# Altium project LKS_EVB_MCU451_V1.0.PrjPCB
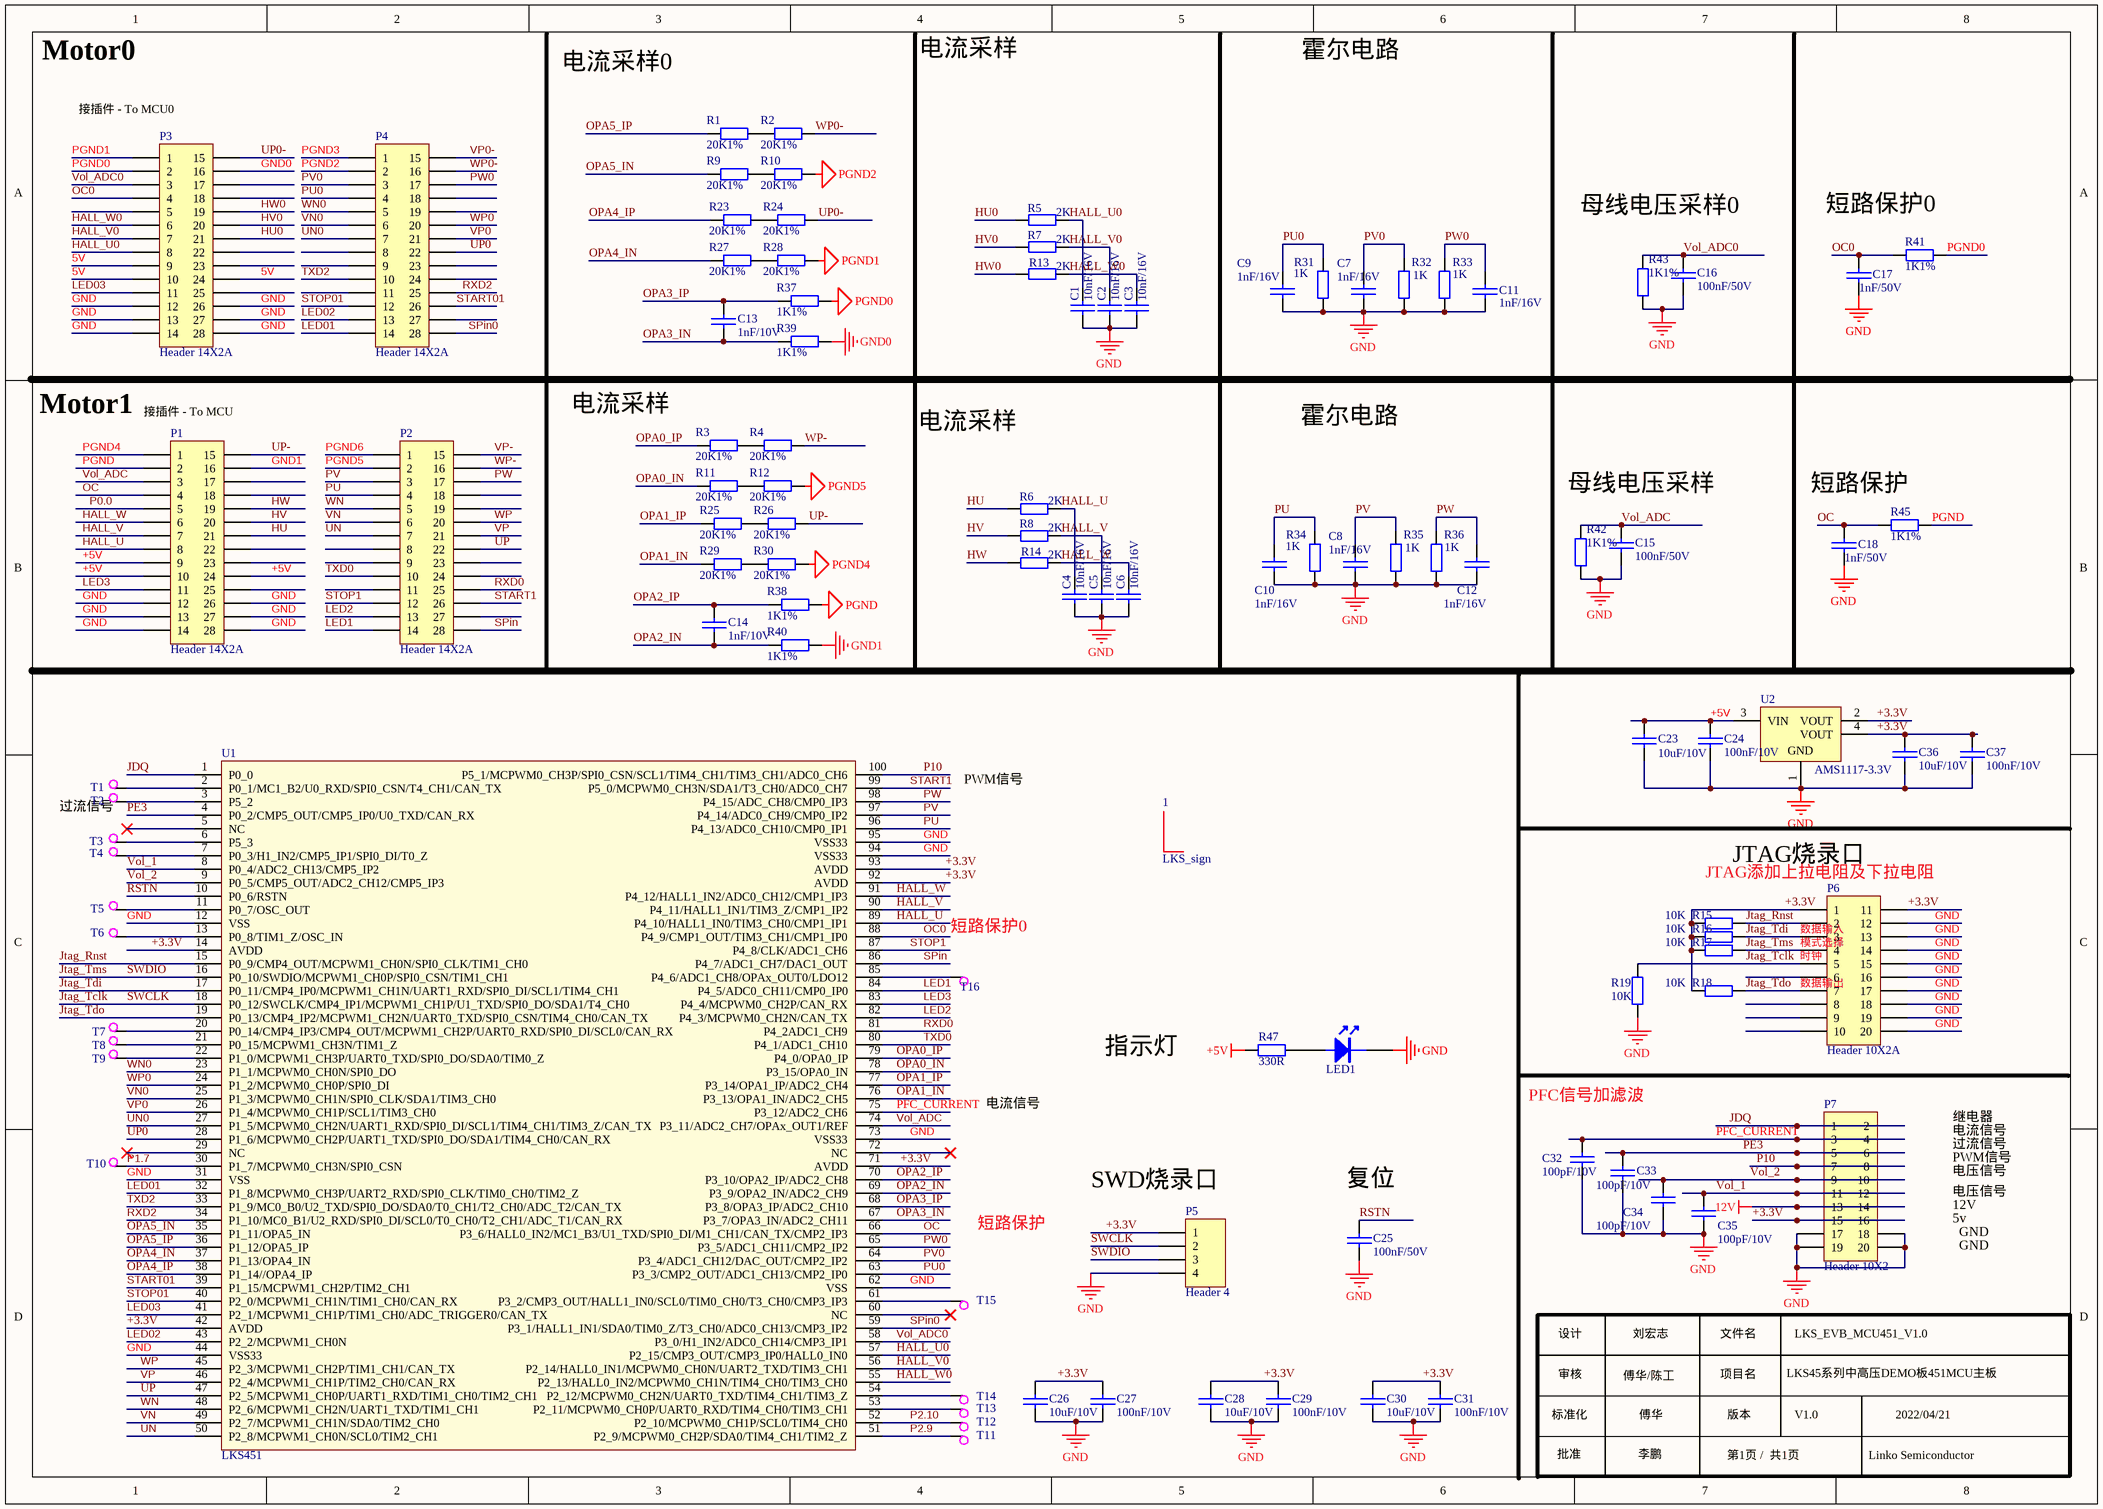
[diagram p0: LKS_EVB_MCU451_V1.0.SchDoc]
1 sheet, 102 parts. Net scope: global (net labels, ports and power ports of the same name join across sheets).
Board file: LKS_EVB_MCU451_V1.0.PcbDoc

## Sheet LKS_EVB_MCU451_V1.0.SchDoc
size A3

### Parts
1  LKS_sign  [LKS_LOGO2]
C1  10nF/16V  [0603C]
C2  10nF/16V  [0603C]
C3  10nF/16V  [0603C]
C4  10nF/16V  [0603C]
C5  10nF/16V  [0603C]
C6  10nF/16V  [0603C]
C7  1nF/16V  [0603C]
C8  1nF/16V  [0603C]
C9  1nF/16V  [0603C]
C10  1nF/16V  [0603C]
C11  1nF/16V  [0603C]
C12  1nF/16V  [0603C]
C13  1nF/10V  [0603C]
C14  1nF/10V  [0603C]
C15  100nF/50V  [0603C]
C16  100nF/50V  [0603C]
C17  1nF/50V  [0603C]
C18  1nF/50V  [0603C]
C23  10uF/10V  [0603C]
C24  100nF/10V  [0603C]
C25  100nF/50V  [0603C]
C26  10uF/10V  [0603C]
C27  100nF/10V  [0603C]
C28  10uF/10V  [0603C]
C29  100nF/10V  [0603C]
C30  10uF/10V  [0603C]
C31  100nF/10V  [0603C]
C32  100pF/10V  [0603C]
C33  100pF/10V  [0603C]
C34  100pF/10V  [0603C]
C35  100pF/10V  [0603C]
C36  10uF/10V  [0603C]
C37  100nF/10V  [0603C]
LED1  LED  [0603D]  (value not drawn)
P1  Header 14X2A  [HDR2X14_CEN]
P2  Header 14X2A  [HDR2X14_CEN]
P3  Header 14X2A  [HDR2X14_CEN]
P4  Header 14X2A  [HDR2X14_CEN]
P5  Header 4  [HDR1X4]
P6  Header 10X2A  [HDR2X10_CEN]
P7  Header 10X2  [HDR2X10]
R1  20K1%  [0603R]
R2  20K1%  [0603R]
R3  20K1%  [0603R]
R4  20K1%  [0603R]
R5  2K  [0603R]
R6  2K  [0603R]
R7  2K  [0603R]
R8  2K  [0603R]
R9  20K1%  [0603R]
R10  20K1%  [0603R]
R11  20K1%  [0603R]
R12  20K1%  [0603R]
R13  2K  [0603R]
R14  2K  [0603R]
R15  10K  [0603R]
R16  10K  [0603R]
R17  10K  [0603R]
R18  10K  [0603R]
R19  10K  [0603R]
R23  20K1%  [0603R]
R24  20K1%  [0603R]
R25  20K1%  [0603R]
R26  20K1%  [0603R]
R27  20K1%  [0603R]
R28  20K1%  [0603R]
R29  20K1%  [0603R]
R30  20K1%  [0603R]
R31  1K  [0603R]
R32  1K  [0603R]
R33  1K  [0603R]
R34  1K  [0603R]
R35  1K  [0603R]
R36  1K  [0603R]
R37  1K1%  [0603R]
R38  1K1%  [0603R]
R39  1K1%  [0603R]
R40  1K1%  [0603R]
R41  1K1%  [0603R]
R42  1K1%  [0603R]
R43  1K1%  [0603R]
R45  1K1%  [0603R]
R47  330R  [0603R]
T1  TestP  [TP-40]  (value not drawn)
T2  TestP  [TP-40]  (value not drawn)
T3  TestP  [TP-40]  (value not drawn)
T4  TestP  [TP-40]  (value not drawn)
T5  TestP  [TP-40]  (value not drawn)
T6  TestP  [TP-40]  (value not drawn)
T7  TestP  [TP-40]  (value not drawn)
T8  TestP  [TP-40]  (value not drawn)
T9  TestP  [TP-40]  (value not drawn)
T10  TestP  [TP-40]  (value not drawn)
T11  TestP  [TP-40]  (value not drawn)
T12  TestP  [TP-40]  (value not drawn)
T13  TestP  [TP-40]  (value not drawn)
T14  TestP  [TP-40]  (value not drawn)
T15  TestP  [TP-40]  (value not drawn)
T16  TestP  [TP-40]  (value not drawn)
U1  LKS451  [LQFP_100N]
U2  AMS1117-3.3V  [DCY0004A_M]

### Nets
12V: P7.13 P7.14
+5V: C23.1 C24.1 P1.9 P1.10 P1.24 R47.1 U2.3(VIN)
GND: C1.2 C2.2 C3.2 C4.2 C5.2 C6.2 C7.2 C8.2 C9.2 C10.2 C11.2 C12.2 C15.1 C16.1 C17.1 C18.1 C23.2 C24.2 C25.2 C26.2 C27.2 C28.2 C29.2 C30.2 C31.2 C32.2 C33.2 C34.2 C35.2 C36.2 C37.2 LED1.2(K) P1.12 P1.13 P1.14 P1.26 P1.27 P1.28 P3.12 P3.13 P3.14 P3.26 P3.27 P3.28 P5.4 P6.12 P6.13 P6.14 P6.15 P6.16 P6.17 P6.18 P6.19 P6.20 P7.17 P7.18 P7.19 P7.20 R19.1 R31.2 R32.2 R33.2 R34.2 R35.2 R36.2 R42.1 R43.1 U1.12(VSS) U1.31(VSS) U1.44(VSS33) U1.62(VSS) U1.73(VSS33) U1.94(VSS33) U1.95(VSS33) U2.1(GND)
GND0: P3.16 R39.1
GND1: P1.16 R40.1
PGND: P1.2 R38.1 R45.2
PGND0: P3.2 R37.1 R41.2
PGND1: P3.1 R28.1
PGND2: P4.2 R10.1
PGND4: P1.1 R30.1
PGND5: P2.2 R12.1
5V: P3.9 P3.10 P3.24
+3.3V: C26.1 C27.1 C28.1 C29.1 C30.1 C31.1 C36.1 C37.1 P5.1 P6.1 P6.11 P7.15 P7.16 R15.1 R16.1 R17.1 R18.1 U1.14(AVDD) U1.42(AVDD) U1.71(AVDD) U1.92(AVDD) U1.93(AVDD) U2.2(VOUT) U2.4(VOUT)
HALL_U: C4.1 P1.8 R6.2 U1.89(P4_10/HALL1_IN0/TIM3_CH0/CMP1_IP1)
HALL_U0: C1.1 P3.8 R5.2 U1.57(P2_15/CMP3_OUT/CMP3_IP0/HALL0_IN0)
HALL_V: C5.1 P1.7 R8.2 U1.90(P4_11/HALL1_IN1/TIM3_Z/CMP1_IP2)
HALL_V0: C2.1 P3.7 R7.2 U1.56(P2_14/HALL0_IN1/MCPWM0_CH0N/UART2_TXD/TIM3_CH1)
HALL_W: C6.1 P1.6 R14.2 U1.91(P4_12/HALL1_IN2/ADC0_CH12/CMP1_IP3)
HALL_W0: C3.1 P3.6 R13.2 U1.55(P2_13/HALL0_IN2/MCPWM0_CH1N/TIM4_CH0/TIM3_CH0)
HU: P1.21 R6.1
HU0: P3.21 R5.1
HV: P1.20 R8.1
HV0: P3.20 R7.1
HW: P1.19 R14.1
HW0: P3.19 R13.1
JDQ: P7.1 P7.2 U1.1(P0_0)
Jtag_Rnst: P6.2 R15.2 U1.15(P0_9/CMP4_OUT/MCPWM1_CH0N/SPI0_CLK/TIM1_CH0)
Jtag_Tclk: P5.2 P6.5 R19.2 U1.18(P0_12/SWCLK/CMP4_IP1/MCPWM1_CH1P/U1_TXD/SPI0_DO/SDA1/T4_CH0)  [also labelled SWCLK]
Jtag_Tdi: P6.3 R16.2 U1.17(P0_11/CMP4_IP0/MCPWM1_CH1N/UART1_RXD/SPI0_DI/SCL1/TIM4_CH1)
Jtag_Tdo: P6.7 R18.2 U1.19(P0_13/CMP4_IP2/MCPWM1_CH2N/UART0_TXD/SPI0_CSN/TIM4_CH0/CAN_TX)
Jtag_Tms: P5.3 P6.4 R17.2 U1.16(P0_10/SWDIO/MCPWM1_CH0P/SPI0_CSN/TIM1_CH1)  [also labelled SWDIO]
LED01: P4.14 U1.32(P1_8/MCPWM0_CH3P/UART2_RXD/SPI0_CLK/TIM0_CH0/TIM2_Z)
LED1: P2.14 U1.84(P4_5/ADC0_CH11/CMP0_IP0)
LED02: P4.13 U1.43(P2_2/MCPWM1_CH0N)
LED2: P2.13 U1.82(P4_3/MCPWM0_CH2N/CAN_TX)
LED03: P3.11 U1.41(P2_1/MCPWM1_CH1P/TIM1_CH0/ADC_TRIGGER0/CAN_TX)
LED3: P1.11 U1.83(P4_4/MCPWM0_CH2P/CAN_RX)
OC: C18.2 P1.4 R45.1 U1.66(P3_6/HALL0_IN2/MC1_B3/U1_TXD/SPI0_DI/M1_CH1/CAN_TX/CMP2_IP3)
OC0: C17.2 P3.4 R41.1 U1.88(P4_9/CMP1_OUT/TIM3_CH1/CMP1_IP0)
OPA0_IN: R11.2 U1.78(P3_15/OPA0_IN)
OPA0_IP: R3.2 U1.79(P4_0/OPA0_IP)
OPA1_IN: R29.2 U1.76(P3_13/OPA1_IN/ADC2_CH5)
OPA1_IP: R25.2 U1.77(P3_14/OPA1_IP/ADC2_CH4)
OPA2_IN: C14.2 R40.2 U1.69(P3_9/OPA2_IN/ADC2_CH9)
OPA2_IP: C14.1 R38.2 U1.70(P3_10/OPA2_IP/ADC2_CH8)
OPA3_IN: C13.2 R39.2 U1.67(P3_7/OPA3_IN/ADC2_CH11)
OPA3_IP: C13.1 R37.2 U1.68(P3_8/OPA3_IP/ADC2_CH10)
OPA4_IN: R27.2 U1.37(P1_13/OPA4_IN)
OPA4_IP: R23.2 U1.38(P1_14//OPA4_IP)
OPA5_IN: R9.2 U1.35(P1_11/OPA5_IN)
OPA5_IP: R1.2 U1.36(P1_12/OPA5_IP)
P0.0: P1.5
P1.7: T10.1 U1.30(P1_7/MCPWM0_CH3N/SPI0_CSN)
P2.9: T11.1 U1.51(P2_9/MCPWM0_CH2P/SDA0/TIM4_CH1/TIM2_Z)
P2.10: T12.1 U1.52(P2_10/MCPWM0_CH1P/SCL0/TIM4_CH0)
P10: P7.7 P7.8 U1.100(P5_1/MCPWM0_CH3P/SPI0_CSN/SCL1/TIM4_CH1/TIM3_CH1/ADC0_CH6)
PE3: C33.1 P7.5 P7.6 U1.4(P0_2/CMP5_OUT/CMP5_IP0/U0_TXD/CAN_RX)
PFC_CURRENT: C32.1 P7.3 P7.4 U1.75(P3_12/ADC2_CH6)
PGND3: P4.1
PGND6: P2.1
PU: C10.1 P2.4 R34.1 U1.96(P4_13/ADC0_CH10/CMP0_IP1)
PU0: C9.1 P4.4 R31.1 U1.63(P3_3/CMP2_OUT/ADC1_CH13/CMP2_IP0)
PV: C8.1 P2.3 R35.1 U1.97(P4_14/ADC0_CH9/CMP0_IP2)
PV0: C7.1 P4.3 R32.1 U1.64(P3_4/ADC1_CH12/DAC_OUT/CMP2_IP2)
PW: C12.1 P2.17 R36.1 U1.98(P4_15/ADC_CH8/CMP0_IP3)
PW0: C11.1 P4.17 R33.1 U1.65(P3_5/ADC1_CH11/CMP2_IP2)
RSTN: C25.1 U1.10(P0_6/RSTN)
RXD0: P2.25 U1.81(P4_2ADC1_CH9)
RXD2: P4.25 U1.34(P1_10/MC0_B1/U2_RXD/SPI0_DI/SCL0/T0_CH0/T2_CH1/ADC_T1/CAN_RX)
SPin: P2.28 U1.86(P4_7/ADC1_CH7/DAC1_OUT)
SPin0: P4.28 U1.59(P3_1/HALL1_IN1/SDA0/TIM0_Z/T3_CH0/ADC0_CH13/CMP3_IP2)
START01: P4.26 U1.39(P1_15/MCPWM1_CH2P/TIM2_CH1)
START1: P2.26 U1.99(P5_0/MCPWM0_CH3N/SDA1/T3_CH0/ADC0_CH7)
STOP01: P4.12 U1.40(P2_0/MCPWM1_CH1N/TIM1_CH0/CAN_RX)
STOP1: P2.12 U1.87(P4_8/CLK/ADC1_CH6)
TXD0: P2.10 U1.80(P4_1/ADC1_CH10)
TXD2: P4.10 U1.33(P1_9/MC0_B0/U2_TXD/SPI0_DO/SDA0/T0_CH1/T2_CH0/ADC_T2/CAN_TX)
UN: P2.7 U1.50(P2_8/MCPWM1_CH0N/SCL0/TIM2_CH1)
UN0: P4.7 U1.27(P1_5/MCPWM0_CH2N/UART1_RXD/SPI0_DI/SCL1/TIM4_CH1/TIM3_Z/CAN_TX)
UP: P2.22 U1.47(P2_5/MCPWM1_CH0P/UART1_RXD/TIM1_CH0/TIM2_CH1)
UP0: P4.22 U1.28(P1_6/MCPWM0_CH2P/UART1_TXD/SPI0_DO/SDA1/TIM4_CH0/CAN_RX)
UP0-: P3.15 R24.1
UP-: P1.15 R26.1
VN: P2.6 U1.49(P2_7/MCPWM1_CH1N/SDA0/TIM2_CH0)
VN0: P4.6 U1.25(P1_3/MCPWM0_CH1N/SPI0_CLK/SDA1/TIM3_CH0)
Vol_1: C35.1 P7.11 P7.12 U1.8(P0_4/ADC2_CH13/CMP5_IP2)
Vol_2: C34.1 P7.9 P7.10 U1.9(P0_5/CMP5_OUT/ADC2_CH12/CMP5_IP3)
Vol_ADC: C15.2 P1.3 R42.2 U1.74(P3_11/ADC2_CH7/OPAx_OUT1/REF)
Vol_ADC0: C16.2 P3.3 R43.2 U1.58(P3_0/H1_IN2/ADC0_CH14/CMP3_IP1)
VP: P2.21 U1.46(P2_4/MCPWM1_CH1P/TIM2_CH0/CAN_RX)
VP0: P4.21 U1.26(P1_4/MCPWM0_CH1P/SCL1/TIM3_CH0)
VP0-: P4.15
VP-: P2.15
WN: P2.5 U1.48(P2_6/MCPWM1_CH2N/UART1_TXD/TIM1_CH1)
WN0: P4.5 U1.23(P1_1/MCPWM0_CH0N/SPI0_DO)
WP: P2.20 U1.45(P2_3/MCPWM1_CH2P/TIM1_CH1/CAN_TX)
WP0: P4.20 U1.24(P1_2/MCPWM0_CH0P/SPI0_DI)
WP0-: P4.16 R2.1
WP-: P2.16 R4.1
NetLED1_1: LED1.1(A) R47.2
NetR1_1: R1.1 R2.2
NetR3_1: R3.1 R4.2
NetR9_1: R9.1 R10.2
NetR11_1: R11.1 R12.2
NetR23_1: R23.1 R24.2
NetR25_1: R25.1 R26.2
NetR27_1: R27.1 R28.2
NetR29_1: R29.1 R30.2
NetT1_1: T1.1 U1.2(P0_1/MC1_B2/U0_RXD/SPI0_CSN/T4_CH1/CAN_TX)
NetT2_1: T2.1 U1.3(P5_2)
NetT3_1: T3.1 U1.6(P5_3)
NetT4_1: T4.1 U1.7(P0_3/H1_IN2/CMP5_IP1/SPI0_DI/T0_Z)
NetT5_1: T5.1 U1.11(P0_7/OSC_OUT)
NetT6_1: T6.1 U1.13(P0_8/TIM1_Z/OSC_IN)
NetT7_1: T7.1 U1.20(P0_14/CMP4_IP3/CMP4_OUT/MCPWM1_CH2P/UART0_RXD/SPI0_DI/SCL0/CAN_RX)
NetT8_1: T8.1 U1.21(P0_15/MCPWM1_CH3N/TIM1_Z)
NetT9_1: T9.1 U1.22(P1_0/MCPWM1_CH3P/UART0_TXD/SPI0_DO/SDA0/TIM0_Z)
NetT13_1: T13.1 U1.53(P2_11/MCPWM0_CH0P/UART0_RXD/TIM4_CH0/TIM3_CH1)
NetT14_1: T14.1 U1.54(P2_12/MCPWM0_CH2N/UART0_TXD/TIM4_CH1/TIM3_Z)
NetT15_1: T15.1 U1.61(P3_2/CMP3_OUT/HALL1_IN0/SCL0/TIM0_CH0/T3_CH0/CMP3_IP3)
NetT16_1: T16.1 U1.85(P4_6/ADC1_CH8/OPAx_OUT0/LDO12)

Not connected (* = marked no-connect by the designer): P1 17 18 22 23 25; P2 8 9 11 18 19 23 24 27; P3 5 17 18 22 23 25; P4 8 9 11 18 19 23 24 27; P6 6 8 9 10; U1 5(NC)* 29(NC)* 60(NC)* 72(NC)*

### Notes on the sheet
- Motor0
- (near P3) 接插件 - To MCU0
- 电流采样0
- 电流采样
- 霍尔电路
- 母线电压采样0
- 短路保护0
- Motor1
- (near P1) 接插件 - To MCU
- 母线电压采样
- 短路保护
- PWM信号
- 过流信号
- JTAG添加上拉电阻及下拉电阻
- JTAG烧录口
- (near T16) 短路保护0
- (near P6) 数据输入
- (near P6) 数据输出
- (near P6) 模式选择
- (near P6) 时钟
- 指示灯
- 电流信号
- PFC信号加滤波
- 继电器
- (near P5) SWD烧录口
- (near C25) 复位
- 电压信号
- 5v
- 12V
- GND
- 设计
- 审核
- 傅华/陈工
- 刘宏志
- 文件名
- 项目名
- LKS45系列中高压DEMO板451MCU主板
- LKS_EVB_MCU451_V1.0
- 标准化
- 批准
- 李鹏
- 傅华
- 版本
- 第1页 /  共1页
- V1.0
- Linko Semiconductor
- 2022/04/21

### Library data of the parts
C1-C12 = CAP: Capacitor
C13-C18 C23-C37 = C: Capacitor
LED1 = LED: LED_Light
P1-P4 = Header 14X2A: Header, 14-Pin, Dual row
P5 = Header 4: Header, 4-Pin
P6 = Header 10X2A: Header, 10-Pin, Dual row
P7 = Header 10X2: Header, 10-Pin, Dual row
R1-R14 R23-R43 R45 = Res: Resistor; Value: K
R15-R19 R47 = Res: Resistor; Value: 330
U1 = LKS32MC451VCT8: LKS32MC451VCT8--chip
U2 = CMP-019-00008-2: Low-Dropout Linear Regulator, 1 A, 3.3 V, 0 to 125 degC, 4-Pin SOT223 (DCY), RoHS, Tape and Reel; Manufacturer: Texas Instruments; Output Voltage: 3.3V; Dropout Voltage: 1.2V; Max Ouput Current: 1A; Min Input Voltage: 2.5V; Nominal Supply Current: 5mA; Outputs: 1; Max Input Voltage: 15V; Min Supply Voltage: 3.2V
